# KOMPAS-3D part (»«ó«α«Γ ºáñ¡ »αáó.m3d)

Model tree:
1. Эскиз:1
2. Операция выдавливания:1
     Расстояние 1 = 4.2; Расстояние 2 = 1.6
3. Эскиз:2
4. Операция выдавливания:2
     Расстояние 1 = 0.5; Расстояние 2 = 1.6
5. Эскиз:3
6. Операция выдавливания:6
     Расстояние 1 = 0.1; Расстояние 2 = 2.4
7. Эскиз:7
8. Операция выдавливания:7
     Расстояние 1 = 0.5; Расстояние 2 = 2.4
9. Эскиз:8
10. Операция выдавливания:8
     Расстояние 1 = 4; Расстояние 2 = 2.4
11. Эскиз:9
12. Операция выдавливания:9
     Расстояние 1 = 5; Расстояние 2 = 2.4
13. Скругление:5
     Радиус = 1.5
14. Скругление:6
     Радиус = 0.2
15. Эскиз:10
16. Операция выдавливания:10
     Расстояние 1 = 5; Расстояние 2 = 2
17. Эскиз:11
18. Вырезать элемент выдавливания:2
     Расстояние 1 = 0.5
19. Эскиз:12
20. Операция выдавливания:11
     Расстояние 1 = 0.5; Расстояние 2 = 2
21. Скругление:7
     Радиус = 0.2
22. Скругление:9
     Радиус = 1
23. Эскиз:14
24. Операция выдавливания:12
     Расстояние 1 = 0.5; Расстояние 2 = 2
25. Массив по концентрической сетке:1  (with: Операция выдавливания:12)  (labels: Экземпляр ( 1, 1 ); Экземпляр ( 1, 2 ); Экземпляр ( 1, 3 ); Экземпляр ( 1, 4 ))
     N 2 = 10; Шаг 2 = 360; Номер 2 = 1
26. Скругление:10
     Радиус = 0.1
27. Скругление:11
     Радиус = 0.1
28. Эскиз:16
29. Операция выдавливания:14
     Расстояние 1 = 4; Расстояние 2 = 1.7
30. Эскиз:19
31. Операция выдавливания:17
     Расстояние 1 = 0.2; Расстояние 2 = 3
32. Эскиз:20
33. Операция выдавливания:18
     Расстояние 1 = 0.2; Расстояние 2 = 1.7
34. Эскиз:21
35. Операция выдавливания:19
     Расстояние 1 = 0.2; Расстояние 2 = 1.7
36. Массив по концентрической сетке:3  (with: Операция выдавливания:19)  (labels: Экземпляр ( 1, 1 ); Экземпляр ( 1, 2 ); Экземпляр ( 1, 3 ); Экземпляр ( 1, 4 ))
     N 2 = 4; Шаг 2 = 360; Номер 2 = 1

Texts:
  поворот задн прав
  Сплав АЛ8  ГОСТ 1583-93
